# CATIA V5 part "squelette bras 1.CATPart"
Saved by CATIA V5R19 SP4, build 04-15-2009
Part number: squelette bras 1
Bounding box of the stored display mesh (mm): x 400 to 600, y 0 to 100, z 0 to 335.41
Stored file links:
  G:\EU_thinkMotion\CFAO_2010\MMS_groupe1\MMS_groupe1\OK\rragonneau\rragonneau\squelette bras 1.CATPart
  G:\EU_thinkMotion\CFAO_2010\MMS_groupe1\MMS_groupe1\OK\rragonneau\rragonneau\Squelette.CATProduct
  G:\EU_thinkMotion\CFAO_2010\MMS_groupe1\MMS_groupe1\OK\rragonneau\rragonneau\squelette de base.CATPart
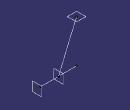
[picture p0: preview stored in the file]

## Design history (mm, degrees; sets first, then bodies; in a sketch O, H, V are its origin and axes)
Parameters
  epaisseur_pneu = 60 mm
Set1
  Line1: type Normal, RefPoint Point1, RefSkin yz-plane, Start -100, End 100
  Line2: type PtPt, FirstPoint Point2, SecondPoint Point1
  Plane1: type OffsetPt, RefPlane yz-plane, RefPoint Point1
  Plane2: type OffsetPt, RefPlane xy-plane, RefPoint Point2
  Plane3: type Offset, RefPlane Plane1, Offset 120 {= epaisseur_pneu*2}
Set2
  Point1: linked copy from another document
  Point2: linked copy from another document
Body1 (main body)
